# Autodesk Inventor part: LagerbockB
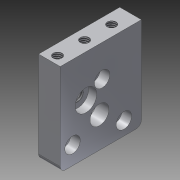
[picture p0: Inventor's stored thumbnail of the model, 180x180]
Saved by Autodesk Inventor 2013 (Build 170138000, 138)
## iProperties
Created: 2012-07
Part Number: LagerbockB
Material: Aluminium 6061
Document SubType Name: Modeling
Designer: rYan
Mass: 19.066 g
Surface Area: 39.1179 cm^2
Volume: 7.03543 cm^3
Density: 2.71 g/cm^3
d0: 30,000 mm
d1: 32,000 mm
d2: 8,000 mm
d3: 0,00 grd
d5: 43,200 mm
d8: 7,000 mm
d15: 12,000 mm
d20: 3,200 mm
d22: 22,000 mm
d24: 35,00 grd
d26: 3,000 mm
d28: 5,500 mm
d29: 3,500 mm
d33: 3,000 oE
d34: 360,00 grd
d36: 30,00 grd
d37: 8,750 mm
d40: 8,000 mm
d41: 4,500 mm
d45: 13,000 mm
d46: 1,000 mm
Author: rYan
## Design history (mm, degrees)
derived "LagerbockA.ipt"
  sketch "Skizze1"
    geometry: L1 (19, 0)-(-23, 0) reference; L2 (0, 40.8)-(0, -6.8) reference; L3 (13, 0)-(-17, 0) reference; L4 (-17, 0)-(-17, 34) reference; L5 (-17, 34)-(13, 34) reference; L6 (13, 34)-(13, 0) reference; 1 further point
  sketch "Skizze3"
    geometry: L1 (-3.5, 15.5)-(-1.433, 15.5) reference; L2 (-3.5, 15.5)-(1.519, 22.668) reference; 1 further point
    constraints: 1 horizontal alignment
  sketch "Skizze4"
    geometry: L1 (-1.519, 22.668)-(-12.519, 22.668) reference; L2 (-1.519, 22.668)-(-10.529, 28.977) reference; C1 r 3.5 at (-1.519, 22.668) reference; A1 r 11 centre (-1.519, 22.668) between (-12.519, 22.668) and (-10.529, 28.977) reference; 2 further points
  sketch "Skizze5"
    geometry: L1 (0, 40.8)-(0, -6.8) reference; L2 (-17, 34)-(13, 34) reference; 2 further points
feature "Volumenkörper1::LagerbockA.ipt"
tag "Bezeichnung1"
node "Volumenkörper1"
other parameters: "d0" = 10, "d1" = 34, "d2" = 8, "d3" = 0, "d15" = 7
